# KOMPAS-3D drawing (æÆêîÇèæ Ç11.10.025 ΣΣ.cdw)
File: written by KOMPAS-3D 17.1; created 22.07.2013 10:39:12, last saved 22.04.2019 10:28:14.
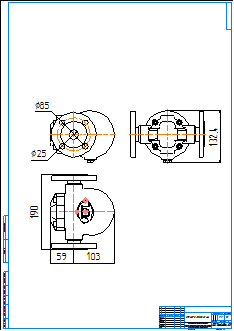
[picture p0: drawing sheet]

Sheet 1: A1, portrait

Title block, sheet 1: name: СТИМАКС А11.10.025 фф; material: Внимание! Данный продукт является объектом авторского права ООО «Торговый Дом АДЛ». / Запрещается изменение, копирование, распространение / (в том числе путем копирования на другие сайты и ресурсы в Интернете) / или любое иное использование информации и объектов без предварительного / согласия правообладателя (ООО «Торговый Дом АДЛ»).; mass: 9,9; sheets: 1; organisation: ООО "Торговый дом АДЛ"; sheet format: A1; stored path: \\adlc.lan\data\АДЛ_ПКД\3D-модели\ADL production\Конденсатоотводчики СТИМАКС\Поплавковые\Серия А11\KOMPAS 2D\СТИМАКС А11.10.025 фф.cdw

Views: Вид 1, Проекционный вид 2, Проекционный вид 3
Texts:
  Klimkovich
  ADL
Dimensions and other numbers on the sheet: 25; 190; 59; 103; 85; 132,4; 1:1; 1; 9,9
